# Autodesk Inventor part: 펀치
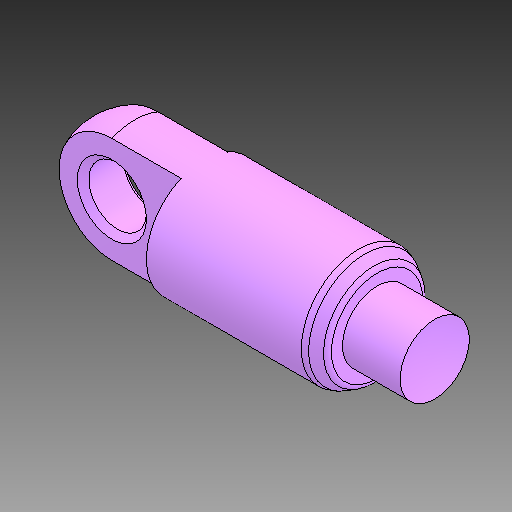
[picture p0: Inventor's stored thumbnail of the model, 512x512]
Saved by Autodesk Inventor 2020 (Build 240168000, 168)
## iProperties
Created: 2024-08
Part Number: 펀치
Material: 강철, 합금
Document SubType Name: Modeling
Designer: 1강의실14
Density: 7.73 g/cm^3
Appearance: 기본값
Author: jhkim
Sending System: Autodesk Inventor 2025
Preprocessor: ST-DEVELOPER v20
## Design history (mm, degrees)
feature "솔리드1"
node "솔리드2"
